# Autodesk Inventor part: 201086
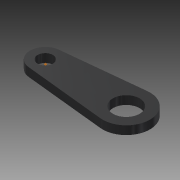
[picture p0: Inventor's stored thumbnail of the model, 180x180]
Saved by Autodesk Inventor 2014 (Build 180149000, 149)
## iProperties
Created: 2007-10
Part Number: 201086
Document SubType Name: Modeling
Designer: TH
Density: 7.85 g/cm^3
Mass: 50.414 g
Surface Area: 38.0293 cm^2
Volume: 6.42217 cm^3
Material: Steel
Description: PIVOT PLATE
Appearance: Rubber - Black - Version 1.1
Component Category: Lower Component
Author: TH
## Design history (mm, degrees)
sketch "Sketch1"
  geometry: L1 (0, 0)-(-48, 0); L2 (-48.938, 8.951)-(-1.458, 13.924); L3 (-48.938, -8.951)-(-1.458, -13.924); A1 r 14 centre (0, 0) between (-1.458, -13.924) and (-1.458, 13.924); A2 r 9 centre (-48, 0) between (-48.938, 8.951) and (-48.938, -8.951); 1 further point
  constraints: 6 end point, 4 point on circle, 4 tangent, 2 centre point, 2 coincident, 1 horizontal
  dimensions: "d0" = 18 diameter of A2; "d1" = 28 diameter of A1; "d2" = 48 distance of point (0, 0) L1.end
extrude "Extrusion1" new body sketch "Sketch1" stored distance "d3" = 5; taper "d4" = 0 deg
sketch "Sketch2"
  geometry: A1 r 14 centre (0, 0) between (-1.458, -13.924) and (-1.458, 13.924) reference
hole "Hole1" sketch "Sketch2" at (0, 0) diameter "d5" = 15.84; stored, may be unused: countersink angle "d9" = 90 deg, drill point angle "d11" = 118 deg; dims "d6" = 6, "d7" = 4, "d8" = 2, "d10" = 8
sketch "Sketch3"
  geometry: A1 r 9 centre (-48, 0) between (-48.938, 8.951) and (-48.938, -8.951) reference
hole "Hole2" sketch "Sketch3" at (-48, 0) diameter "d12" = 9; stored, may be unused: countersink angle "d16" = 90 deg, drill point angle "d18" = 118 deg; dims "d13" = 6, "d14" = 4, "d15" = 2, "d17" = 8
workpoint "Work Point1"
  workaxis "Work Axis1"
body "Solid1"
